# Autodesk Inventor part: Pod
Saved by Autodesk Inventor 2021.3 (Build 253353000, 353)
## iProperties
Created: 2022-07
Part Number: Pod
Material: Generic
Document SubType Name: Modeling
Designer: Administrator
Density: 1 g/cm^3
Appearance: Default
Title: Pod v4
Author: Administrator
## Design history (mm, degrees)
feature "Pod" [Body]
feature "Socket Body" [Body]
feature "Shade Ring" [Body]
feature "Shade Ring +Collar" [Body]
feature "Socket" [Body]
feature "Body1"
feature "Metal Strain Relief" [Body]
feature "Fabric Cord (1)" [Body]
feature "Stem (Threaded)" [Body]
feature "Cap (Threaded)" [Body]
feature "T8-Bulb" [Body]
body "Solid1"
body "Solid2"
body "Solid3"
body "Solid4"
body "Solid5"
body "Solid6"
body "Solid7"
body "Solid8"
body "Solid9"
body "Solid10"
body "Solid11"
